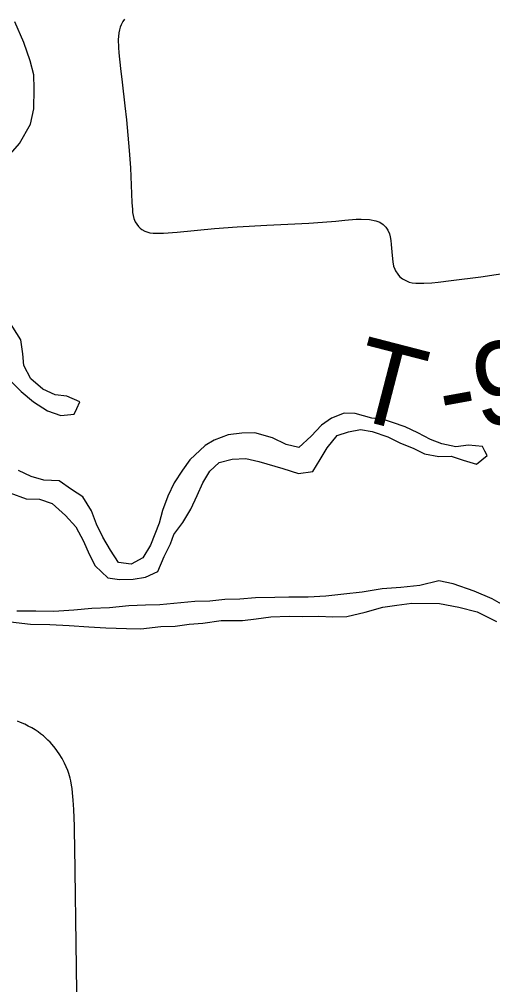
# Model space of a CAD drawing. Extents: x 0 to 34, y -5.4 to 22.
# Drawn here: x 3.525 to 3.849, y 19.626 to 20.286 of the extents above; entities that cross this region are included whole.
import ezdxf

# ---------------------------------------------------------------- set-up
doc = ezdxf.new("R2010")
doc.units = 0
for name, color, linetype in [('GM_X_Major_Lake', 7, 'Continuous'), ('GM_X_Major_River', 7, 'Continuous'), ('GM_X_Minor_River', 7, 'Continuous'), ('GM_X_State_Route', 7, 'Continuous'), ('GM_X_Township_Road', 7, 'Continuous'), ('GM_X_Township_Road_Text', 7, 'Continuous')]:
    doc.layers.add(name, color=color, linetype=linetype)

msp = doc.modelspace()

# ---------------------------------------------------------------- linework, layer by layer
at = {"layer": 'GM_X_Major_Lake'}
msp.add_lwpolyline([(3.51461, 20.18884), (3.52541, 20.20119), (3.53281, 20.21436), (3.53524, 20.22495), (3.53545, 20.23862), (3.53522, 20.24811), (3.53271, 20.25763), (3.52835, 20.27023), (3.52213, 20.28437)], dxfattribs=at)
at = {"layer": 'GM_X_Major_River'}
for points in [[(3.56457, 20.02), (3.56667, 20.02443), (3.55763, 20.02837), (3.54969, 20.02926), (3.54141, 20.03318), (3.53318, 20.04014), (3.52839, 20.04933), (3.52776, 20.0573), (3.52639, 20.06682), (3.52084, 20.07563), (3.51528, 20.08407), (3.5082, 20.09215), (3.50032, 20.09721), (3.49096, 20.10457), (3.48273, 20.11153), (3.47871, 20.12108), (3.47696, 20.13097), (3.47728, 20.13992), (3.47836, 20.14765)], [(3.45457, 20.09943), (3.4648, 20.10384), (3.47232, 20.09992), (3.48054, 20.09183), (3.48882, 20.08828), (3.49745, 20.08283), (3.50529, 20.07474), (3.51121, 20.06554), (3.51408, 20.05524), (3.51623, 20.04686), (3.51914, 20.03884), (3.52661, 20.03151), (3.53484, 20.02455), (3.5446, 20.01833), (3.55364, 20.01515), (3.56275, 20.01615), (3.56457, 20.02)], [(3.84344, 19.99074), (3.8417, 19.99394), (3.83224, 19.99485), (3.82351, 19.99385), (3.81406, 19.99589), (3.80615, 19.99868), (3.7975, 20.00336), (3.78885, 20.0073), (3.78018, 20.01047), (3.77415, 20.01246), (3.7662, 20.01334), (3.75488, 20.01655), (3.74731, 20.01668), (3.73854, 20.0134), (3.73165, 20.00857), (3.72471, 20.00109), (3.71626, 19.99325), (3.70757, 19.99528), (3.69817, 19.99998), (3.68609, 20.00321), (3.67737, 20.00297), (3.66788, 20.00198), (3.65835, 19.99833), (3.65223, 19.99463), (3.64185, 19.98492), (3.63682, 19.97779), (3.631, 19.96915), (3.6267, 19.96011), (3.62313, 19.9503), (3.62073, 19.94161), (3.61481, 19.92651), (3.60976, 19.91787), (3.60173, 19.91344), (3.59303, 19.91471), (3.58748, 19.92315), (3.58231, 19.93196), (3.57789, 19.94076), (3.57462, 19.94992), (3.56871, 19.9595), (3.56083, 19.96456), (3.55258, 19.97038), (3.54198, 19.97092), (3.5333, 19.97334), (3.52465, 19.97765)], [(3.62847, 19.92744), (3.63084, 19.93385), (3.63703, 19.94211), (3.64247, 19.95113), (3.64679, 19.96055), (3.65071, 19.96922), (3.65538, 19.97712), (3.66191, 19.98309), (3.67066, 19.98523), (3.68014, 19.98584), (3.68883, 19.98381), (3.70543, 19.97899), (3.71598, 19.97541), (3.72586, 19.97678), (3.73091, 19.98505), (3.73558, 19.99295), (3.74253, 20.00157), (3.75015, 20.0041), (3.7585, 20.00549), (3.76644, 20.00423), (3.777, 20.00065), (3.78565, 19.99634), (3.79431, 19.99279), (3.80221, 19.98887), (3.81204, 19.98719), (3.82038, 19.98744), (3.82867, 19.98466), (3.83772, 19.98186), (3.84501, 19.98782), (3.84344, 19.99074)], [(3.51873, 19.96218), (3.53003, 19.9582), (3.53913, 19.95806), (3.5478, 19.95489), (3.55677, 19.94678), (3.56385, 19.93908), (3.569, 19.92913), (3.57303, 19.92034), (3.57708, 19.9123), (3.58567, 19.9042), (3.59361, 19.90293), (3.60309, 19.90316), (3.61145, 19.90455), (3.61985, 19.9086), (3.62417, 19.91878), (3.62847, 19.92744)]]:
    msp.add_lwpolyline(points, dxfattribs=at)
at = {"layer": 'GM_X_Minor_River'}
for points in [[(3.86272, 19.88164), (3.84845, 19.88984), (3.83602, 19.89497), (3.8217, 19.90012), (3.81188, 19.90218), (3.79894, 19.89896), (3.78604, 19.89765), (3.77314, 19.89671), (3.75946, 19.89427), (3.74694, 19.89294), (3.73479, 19.89162), (3.72265, 19.89105), (3.70939, 19.89088), (3.69991, 19.89064), (3.68664, 19.89047), (3.67602, 19.8895), (3.66578, 19.88928), (3.65554, 19.8883), (3.6453, 19.88808), (3.62139, 19.8858), (3.61154, 19.88557), (3.60016, 19.88499), (3.58688, 19.88368), (3.57474, 19.88311), (3.5626, 19.88216), (3.54894, 19.88124), (3.53644, 19.88144), (3.52356, 19.88126)], [(3.51928, 19.87411), (3.53289, 19.87238), (3.54615, 19.87217), (3.55941, 19.87159), (3.57266, 19.87062), (3.5844, 19.87006), (3.59841, 19.86946), (3.60826, 19.8693), (3.62193, 19.87099), (3.63178, 19.87121), (3.64128, 19.87258), (3.65076, 19.87319), (3.66329, 19.8749), (3.67769, 19.87505), (3.68718, 19.87604), (3.69706, 19.8774), (3.70957, 19.87797), (3.71904, 19.87782), (3.72966, 19.87803), (3.7395, 19.8775), (3.74898, 19.87773), (3.76153, 19.88057), (3.77371, 19.88418), (3.7832, 19.88555), (3.79345, 19.8869), (3.8124, 19.88661), (3.82562, 19.88412), (3.83808, 19.88089), (3.85124, 19.87423)]]:
    msp.add_lwpolyline(points, dxfattribs=at)
at = {"layer": 'GM_X_State_Route'}
msp.add_lwpolyline([(3.56537, 19.55521), (3.56317, 19.7203), (3.56303, 19.73044), (3.56296, 19.73444), (3.56282, 19.74016), (3.56255, 19.74586), (3.5621, 19.75205), (3.56164, 19.75718), (3.56133, 19.76004), (3.56092, 19.76241), (3.56036, 19.76532), (3.55992, 19.76722), (3.55903, 19.7704), (3.55831, 19.77251), (3.55729, 19.77497), (3.55618, 19.77736), (3.55446, 19.78056), (3.55245, 19.78378), (3.54966, 19.78764), (3.54766, 19.79016), (3.54629, 19.79172), (3.54483, 19.79321), (3.54301, 19.79492), (3.54168, 19.79602), (3.53968, 19.79758), (3.53808, 19.79875), (3.53601, 19.80012), (3.53372, 19.80154), (3.53136, 19.8028), (3.52904, 19.804), (3.52613, 19.80533), (3.52401, 19.80617)], dxfattribs=at)
at = {"layer": 'GM_X_Township_Road'}
for points in [[(3.59702, 20.28607), (3.59609, 20.28463), (3.59488, 20.2823), (3.5942, 20.2807), (3.59367, 20.27878), (3.5933, 20.27691), (3.59296, 20.27427), (3.59284, 20.27233), (3.59296, 20.26671), (3.59322, 20.26317), (3.59433, 20.25253), (3.59551, 20.24315), (3.59739, 20.22689), (3.5984, 20.21732), (3.60036, 20.1963), (3.60115, 20.18444), (3.60171, 20.17274), (3.60211, 20.16092), (3.60253, 20.15591), (3.60269, 20.15406), (3.60302, 20.15191), (3.6036, 20.14981), (3.60446, 20.14753), (3.60553, 20.14592), (3.60669, 20.14438), (3.60784, 20.14334), (3.60907, 20.14234), (3.61097, 20.14131), (3.61247, 20.14071), (3.61452, 20.14016), (3.61664, 20.13993), (3.61887, 20.13982), (3.62062, 20.13973), (3.62259, 20.13979), (3.62381, 20.13983), (3.63316, 20.14059), (3.65854, 20.14292), (3.67403, 20.14412), (3.6945, 20.14531), (3.72306, 20.14663), (3.73855, 20.14771), (3.74157, 20.14804)], [(3.74157, 20.14804), (3.74761, 20.14868), (3.75542, 20.14932), (3.75897, 20.14948), (3.76455, 20.1491), (3.76882, 20.14828), (3.77162, 20.14737), (3.77398, 20.14583), (3.7757, 20.14384), (3.77706, 20.14194), (3.77815, 20.13941), (3.77869, 20.13732), (3.77906, 20.13479), (3.77942, 20.13198), (3.78006, 20.12455), (3.78051, 20.12021), (3.78106, 20.11731), (3.78184, 20.11517), (3.78239, 20.11399), (3.78388, 20.1118), (3.78513, 20.11028), (3.78702, 20.10871), (3.78849, 20.10782), (3.79174, 20.10642), (3.79383, 20.10581), (3.79619, 20.10555), (3.79863, 20.10555), (3.80171, 20.10555), (3.80722, 20.10588), (3.81147, 20.10637), (3.82041, 20.10739), (3.84075, 20.10994), (3.86901, 20.11432)]]:
    msp.add_lwpolyline(points, dxfattribs=at)

# ---------------------------------------------------------------- texts
at = {"layer": 'GM_X_Township_Road_Text'}
for s, rotation, p in [('T', 345.50227, (3.74849, 20.0146)), ('9', 6.61833, (3.83824, 20.00704)), ('-', 10.3247, (3.81625, 20.00299))]:
    msp.add_text(s, height=0.05682, rotation=rotation, dxfattribs=at).set_placement(p)

doc.saveas('drawing.dxf')
